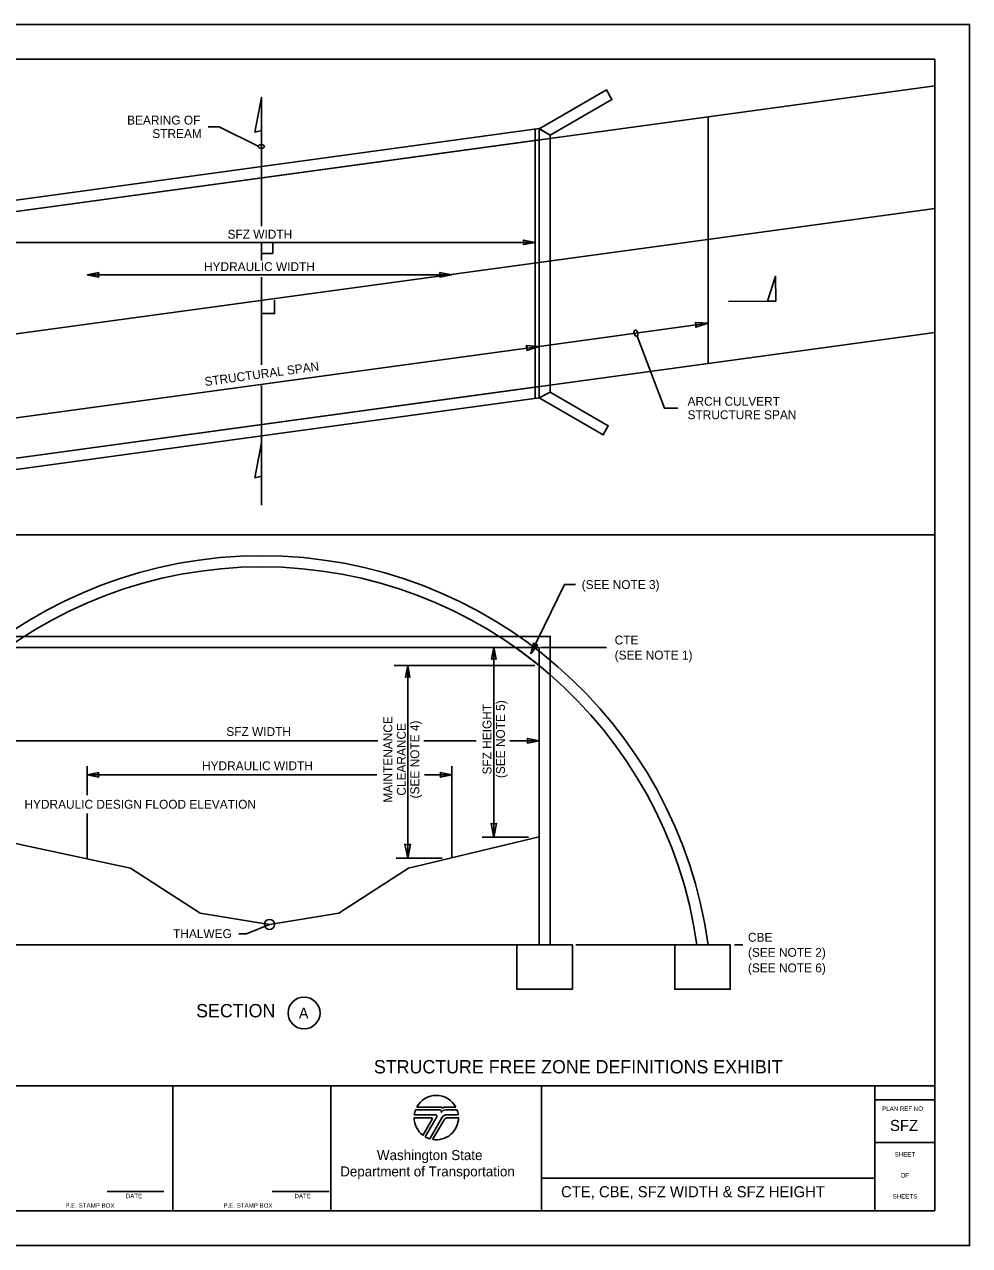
# Model space of a CAD drawing. Extents: x 99988 to 100090, y 99986 to 100024.
# Drawn here: x 100067.61 to 100076.12, y 99999.62 to 100010.62 of the extents above; entities that cross this region are included whole.
import ezdxf

# ---------------------------------------------------------------- set-up
doc = ezdxf.new("R2010")
doc.units = 0
for name, color, linetype in [('Default', 7, 'Continuous'), ('Level 1', 7, 'Continuous'), ('Level 15', 7, 'Continuous'), ('Level 17', 7, 'Continuous'), ('Level 20', 7, 'Continuous'), ('Level 22', 7, 'Continuous'), ('Level 4', 7, 'Continuous'), ('Level 6', 7, 'Continuous'), ('Level 8', 7, 'Continuous'), ('RD_ED_RoadwayETWPaved', 7, 'Continuous'), ('SH_GI_PlotLimits', 7, 'Continuous'), ('SH_GI_SheetBorder', 7, 'Continuous'), ('SH_GI_SheetTextInCells', 7, 'Continuous'), ('SH_GI_WSDOTLogo', 7, 'Continuous'), ('TP_NT_Thalweg', 7, 'Continuous')]:
    doc.layers.add(name, color=color, linetype=linetype)

msp = doc.modelspace()

# ---------------------------------------------------------------- linework, layer by layer
at = {"layer": 'Default'}
for p, q in [((100072.21, 100008.512), (100072.21, 100008.812)), ((100074.006, 100002.334), (100074.082, 100002.334))]:
    msp.add_line(p, q, dxfattribs=at)
msp.add_circle((100069.817, 100002.518), 0.0451, dxfattribs=at)
at = {"layer": 'Level 1'}
msp.add_lwpolyline([(100073.669, 100002.334), (100073.469, 100002.334), (100073.469, 100001.934), (100073.669, 100001.934), (100073.969, 100001.934), (100073.969, 100002.334), (100073.769, 100002.334), (100073.669, 100002.334)], dxfattribs=at)
at = {"layer": 'Level 15'}
for p, q in [((100063.679, 100007.311), (100075.812, 100008.968)), ((100067.272, 100008.662), (100072.21, 100008.662)), ((100069.846, 100008.562), (100069.846, 100008.662)), ((100069.746, 100008.562), (100069.846, 100008.562)), ((100068.174, 100008.37), (100071.46, 100008.37)), ((100067.246, 100007.042), (100072.246, 100007.725)), ((100071.838, 100005.012), (100071.838, 100003.305)), ((100072.259, 100005.012), (100072.853, 100005.012)), ((100072.208, 100004.85), (100070.939, 100004.85)), ((100071.062, 100004.85), (100071.062, 100003.116)), ((100067.246, 100004.172), (100070.794, 100004.172)), ((100071.209, 100004.172), (100071.68, 100004.172)), ((100071.982, 100004.172), (100072.246, 100004.172)), ((100068.174, 100003.944), (100068.174, 100003.683)), ((100068.174, 100003.864), (100070.783, 100003.864)), ((100071.213, 100003.864), (100071.46, 100003.864)), ((100071.46, 100003.944), (100071.46, 100003.119)), ((100068.174, 100003.517), (100068.174, 100003.109)), ((100071.734, 100003.305), (100072.151, 100003.305)), ((100070.958, 100003.116), (100071.374, 100003.116)), ((100072.577, 100002.334), (100073.871, 100002.334))]:
    msp.add_line(p, q, dxfattribs=at)
for points in [[(100069.714, 100009.527), (100069.363, 100009.703), (100069.263, 100009.703)], [(100069.862, 100008.14), (100069.862, 100008.021), (100069.746, 100008.021)], [(100073.13, 100007.817), (100073.375, 100007.169), (100073.496, 100007.169)], [(100072.172, 100004.959), (100072.475, 100005.579), (100072.575, 100005.579)], [(100069.817, 100002.518), (100069.611, 100002.433), (100069.541, 100002.433)]]:
    msp.add_lwpolyline(points, dxfattribs=at)
for points in [[(100072.21, 100008.662), (100072.105, 100008.642), (100072.11, 100008.662), (100072.105, 100008.683)], [(100068.174, 100008.37), (100068.279, 100008.349), (100068.274, 100008.37), (100068.279, 100008.39)], [(100071.456, 100008.37), (100071.351, 100008.349), (100071.356, 100008.37), (100071.351, 100008.39)], [(100073.769, 100007.933), (100073.654, 100007.941), (100073.662, 100007.92), (100073.659, 100007.897)], [(100072.246, 100007.725), (100072.131, 100007.733), (100072.139, 100007.712), (100072.136, 100007.689)], [(100071.838, 100005.012), (100071.859, 100004.907), (100071.838, 100004.912), (100071.818, 100004.907)], [(100072.172, 100004.956), (100072.197, 100005.053), (100072.212, 100005.04), (100072.232, 100005.036)], [(100071.062, 100004.85), (100071.082, 100004.745), (100071.062, 100004.75), (100071.041, 100004.745)], [(100072.246, 100004.172), (100072.141, 100004.152), (100072.146, 100004.172), (100072.141, 100004.193)], [(100068.174, 100003.864), (100068.279, 100003.843), (100068.274, 100003.864), (100068.279, 100003.885)], [(100071.46, 100003.864), (100071.355, 100003.843), (100071.36, 100003.864), (100071.355, 100003.885)], [(100071.838, 100003.305), (100071.863, 100003.428), (100071.838, 100003.423), (100071.814, 100003.428)], [(100071.062, 100003.116), (100071.086, 100003.24), (100071.062, 100003.234), (100071.037, 100003.24)]]:
    msp.add_lwpolyline(points, close=True, dxfattribs=at)
for centre, major_axis in [((100069.743, 100009.525), (-0.0288, 0)), ((100073.119, 100007.844), (-0.0091, 0.0273))]:
    msp.add_ellipse(centre, major_axis=major_axis, ratio=0.57735, dxfattribs=at)
at = {"layer": 'Level 17'}
msp.add_line((100071.46, 100003.864), (100071.36, 100003.864), dxfattribs=at)
at = {"layer": 'Level 20'}
msp.add_line((100073.953, 100008.13), (100074.378, 100008.131), dxfattribs=at)
msp.add_lwpolyline([(100074.303, 100008.131), (100074.377, 100008.356), (100074.378, 100008.131)], close=True, dxfattribs=at)
msp.add_circle((100070.128, 100001.72), 0.144, dxfattribs=at)
at = {"layer": 'Level 22'}
for points in [[(100072.246, 100009.685), (100072.852, 100010.035), (100072.902, 100009.948), (100072.346, 100009.627), (100072.246, 100009.685)], [(100067.246, 100009.002), (100072.246, 100009.686), (100072.246, 100009.585), (100067.246, 100008.902)], [(100072.246, 100009.686), (100072.346, 100009.627), (100072.346, 100007.312), (100072.246, 100007.261)], [(100067.246, 100006.679), (100072.246, 100007.362), (100072.246, 100007.261), (100067.246, 100006.578)], [(100072.346, 100007.312), (100072.346, 100007.312), (100072.869, 100007.01), (100072.822, 100006.928), (100072.246, 100007.261)], [(100067.146, 100005.112), (100072.346, 100005.112), (100072.346, 100005.012), (100072.346, 100002.334), (100072.246, 100002.334), (100072.246, 100004.85), (100072.033, 100005.012), (100067.459, 100005.012), (100067.246, 100004.85), (100067.246, 100002.334), (100067.146, 100002.334), (100067.146, 100005.012)]]:
    msp.add_lwpolyline(points, close=True, dxfattribs=at)
msp.add_lwpolyline([(100072.246, 100002.334), (100072.046, 100002.334), (100072.046, 100001.934), (100072.246, 100001.934), (100072.546, 100001.934), (100072.546, 100002.334), (100072.346, 100002.334), (100072.246, 100002.334)], dxfattribs=at)
at = {"layer": 'Level 4'}
msp.add_line((100072.21, 100007.256), (100072.21, 100009.681), dxfattribs=at)
msp.add_lwpolyline([(100067.246, 100005.012), (100072.246, 100005.012), (100072.246, 100002.334), (100067.246, 100002.334)], close=True, dxfattribs=at)
at = {"layer": 'Level 6'}
msp.add_lwpolyline([(100067.246, 100003.307), (100068.564, 100003.026), (100069.193, 100002.62), (100069.817, 100002.518), (100070.441, 100002.62), (100071.069, 100003.026), (100072.246, 100003.307)], dxfattribs=at)
at = {"layer": 'Level 8'}
for p, q in [((100073.769, 100009.793), (100073.769, 100007.57)), ((100072.246, 100007.725), (100073.769, 100007.933))]:
    msp.add_line(p, q, dxfattribs=at)
for points in [[(100069.684, 100009.653), (100069.746, 100009.968), (100069.746, 100009.668)], [(100069.684, 100006.541), (100069.746, 100006.855), (100069.746, 100006.556)]]:
    msp.add_lwpolyline(points, close=True, dxfattribs=at)
for radius, start, end in [(4.062, 7.8759, 172.1241), (3.962, 8.076, 171.924)]:
    msp.add_arc((100069.746, 100001.777), radius, start, end, dxfattribs=at)
at = {"layer": 'RD_ED_RoadwayETWPaved'}
for p, q in [((100063.679, 100008.414), (100075.812, 100010.072)), ((100063.679, 100006.191), (100075.812, 100007.849))]:
    msp.add_line(p, q, dxfattribs=at)
at = {"layer": 'SH_GI_PlotLimits'}
msp.add_lwpolyline([(100059.125, 99999.625), (100076.125, 99999.625), (100076.125, 100010.625), (100059.125, 100010.625)], close=True, dxfattribs=at)
at = {"layer": 'SH_GI_SheetBorder'}
for p, q in [((100060.062, 100010.312), (100075.812, 100010.312)), ((100075.812, 100010.312), (100075.812, 99999.937)), ((100075.812, 100006.026), (100063.679, 100006.026)), ((100060.062, 100001.063), (100075.812, 100001.063)), ((100068.945, 99999.937), (100068.945, 100001.063)), ((100070.371, 100001.063), (100070.371, 99999.937)), ((100072.268, 100001.063), (100072.268, 99999.937)), ((100075.27, 100001.063), (100075.27, 99999.937)), ((100075.27, 100000.938), (100075.812, 100000.938)), ((100075.27, 100000.555), (100075.812, 100000.555)), ((100072.268, 100000.233), (100075.27, 100000.233)), ((100068.353, 100000.111), (100068.865, 100000.111)), ((100069.842, 100000.111), (100070.354, 100000.111)), ((100060.062, 99999.937), (100075.812, 99999.937))]:
    msp.add_line(p, q, dxfattribs=at)
at = {"layer": 'SH_GI_WSDOTLogo'}
for p, q in [((100071.121, 100000.804), (100071.312, 100000.804)), ((100071.352, 100000.847), (100071.132, 100000.847)), ((100071.365, 100000.873), (100071.144, 100000.873)), ((100071.324, 100000.784), (100071.219, 100000.605)), ((100071.495, 100000.873), (100071.398, 100000.873)), ((100071.507, 100000.847), (100071.405, 100000.847)), ((100071.405, 100000.847), (100071.405, 100000.847)), ((100071.418, 100000.804), (100071.518, 100000.804)), ((100071.12, 100000.777), (100071.277, 100000.777)), ((100071.284, 100000.765), (100071.199, 100000.618)), ((100071.261, 100000.586), (100071.371, 100000.776)), ((100071.287, 100000.58), (100071.387, 100000.753)), ((100071.428, 100000.777), (100071.52, 100000.777))]:
    msp.add_line(p, q, dxfattribs=at)
for centre, radius, start, end in [((100071.32, 100000.778), 0.2, 28.4787, 151.532), ((100071.32, 100000.778), 0.2, 159.696, 172.5057), ((100071.312, 100000.79), 0.0131, 329.7683, 90), ((100071.352, 100000.832), 0.0148, 327.8418, 89.9985), ((100071.405, 100000.798), 0.0484, 89.9953, 147.8238), ((100071.365, 100000.864), 0.00903, 329.8742, 90.0033), ((100071.418, 100000.749), 0.0542, 90, 149.9974), ((100071.398, 100000.844), 0.0287, 90.0072, 148.1676), ((100071.32, 100000.778), 0.2, 7.4943, 20.2941), ((100071.32, 100000.778), 0.2, 179.9986, 232.8433), ((100071.277, 100000.769), 0.0082, 329.7436, 90), ((100071.32, 100000.778), 0.2, 260.5455, 359.8086), ((100071.428, 100000.729), 0.0476, 90, 150.0543), ((100071.32, 100000.778), 0.2, 239.7929, 253.0448)]:
    msp.add_arc(centre, radius, start, end, dxfattribs=at)
at = {"layer": 'TP_NT_Thalweg'}
for p, q in [((100069.746, 100008.808), (100069.746, 100009.968)), ((100069.746, 100008.497), (100069.746, 100008.664)), ((100069.746, 100007.558), (100069.746, 100008.349)), ((100069.746, 100006.295), (100069.746, 100007.371))]:
    msp.add_line(p, q, dxfattribs=at)

# ---------------------------------------------------------------- texts
at = {"layer": 'Level 15'}
msp.add_text('STRUCTURAL SPAN', height=0.08, rotation=7.7791, dxfattribs=at).set_placement((100069.237, 100007.367))
at = {"layer": 'Level 20'}
for s, height, p in [('BEARING OF', 0.08, (100068.534, 100009.723)), ('STREAM', 0.08, (100068.761, 100009.602)), ('ARCH CULVERT', 0.08, (100073.584, 100007.19)), ('STRUCTURE SPAN', 0.08, (100073.584, 100007.069)), ('(SEE NOTE 3)', 0.08, (100072.63, 100005.539)), ('CTE ', 0.08, (100072.927, 100005.04)), ('(SEE NOTE 1)', 0.08, (100072.927, 100004.904)), ('HYDRAULIC DESIGN FLOOD ELEVATION', 0.08, (100067.609, 100003.56)), ('THALWEG', 0.08, (100068.948, 100002.395)), ('CBE ', 0.08, (100074.128, 100002.362)), ('(SEE NOTE 2)', 0.08, (100074.128, 100002.226)), ('(SEE NOTE 6)', 0.08, (100074.128, 100002.086)), ('SECTION ', 0.12, (100069.156, 100001.681)), ('A', 0.096, (100070.082, 100001.672)), ('STRUCTURE FREE ZONE DEFINITIONS EXHIBIT', 0.12, (100070.758, 100001.176)), ('SFZ', 0.1, (100075.408, 100000.657)), ('CTE, CBE, SFZ WIDTH & SFZ HEIGHT', 0.1, (100072.444, 100000.06))]:
    msp.add_text(s, height=height, dxfattribs=at).set_placement(p)
for s, rotation, p in [('SFZ WIDTH', 360, (100069.439, 100008.695)), ('HYDRAULIC WIDTH', 360, (100069.227, 100008.403)), ('(SEE NOTE 5)', 90, (100071.938, 100003.836)), ('SFZ HEIGHT', 90, (100071.817, 100003.868)), ('MAINTENANCE', 90, (100070.924, 100003.615)), ('CLEARANCE', 90, (100071.045, 100003.678)), ('(SEE NOTE 4)', 90, (100071.166, 100003.653)), ('SFZ WIDTH', 360, (100069.428, 100004.215)), ('HYDRAULIC WIDTH', 360, (100069.209, 100003.907))]:
    msp.add_text(s, height=0.08, rotation=rotation, dxfattribs=at).set_placement(p)
at = {"layer": 'SH_GI_SheetBorder'}
msp.add_text('PLAN REF NO', height=0.04003, dxfattribs=at).set_placement((100075.337, 100000.838))
at = {"layer": 'SH_GI_SheetTextInCells'}
for s, height, p in [('Washington State', 0.09007, (100070.785, 100000.395)), ('SHEET', 0.04, (100075.45, 100000.427)), ('Department of Transportation', 0.09007, (100070.454, 100000.248)), ('OF', 0.04, (100075.503, 100000.238)), ('DATE', 0.04, (100068.522, 100000.052)), ('DATE', 0.04, (100070.042, 100000.052)), ('SHEETS', 0.04, (100075.432, 100000.049)), ('P.E. STAMP BOX', 0.04003, (100067.978, 99999.966)), ('P.E. STAMP BOX', 0.04003, (100069.402, 99999.966))]:
    msp.add_text(s, height=height, dxfattribs=at).set_placement(p)

doc.saveas('drawing.dxf')
